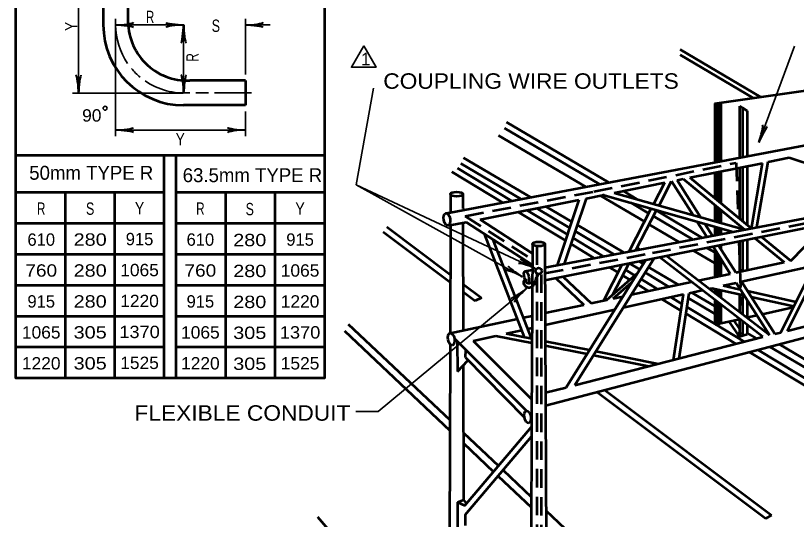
# Model space of a CAD drawing. Extents: x -111 to 744, y -77 to 467.
# Drawn here: x 347.6 to 499.2, y 245.3 to 343 of the extents above; entities that cross this region are included whole.
import ezdxf
from ezdxf.enums import TextEntityAlignment as Align

# ---------------------------------------------------------------- set-up
doc = ezdxf.new("R2010")
doc.units = 0
doc.header["$LTSCALE"] = 1.2
doc.header["$PDMODE"] = 32
doc.header["$PDSIZE"] = 0.6
doc.linetypes.add('MEDIUM_DASHED', pattern=[4.5, 3, -1.5])
doc.layers.add('1', color=7, linetype='Continuous', lineweight=53)

msp = doc.modelspace()

# ---------------------------------------------------------------- linework, layer by layer
at = {"layer": '1', "lineweight": 35}
for p, q in [((359.809, 353.245), (359.809, 328.032)), ((367.009, 342.445), (367.009, 341.245)), ((367.009, 341.247), (367.009, 319.645)), ((380.209, 341.232), (367.009, 341.232)), ((380.209, 341.232), (380.209, 328.045)), ((392.209, 331.645), (392.209, 342.432)), ((392.209, 341.232), (397.009, 341.232)), ((491.87, 318.43), (498.816, 337.139)), ((413.7, 310.233), (417.064, 329.002)), ((380.089, 328.032), (358.609, 328.032)), ((385.009, 328.045), (382.609, 328.045)), ((393.409, 328.045), (386.209, 328.045)), ((392.209, 324.445), (392.209, 319.645)), ((367.009, 320.845), (392.209, 320.845))]:
    msp.add_line(p, q, dxfattribs=at)
at = {"layer": '1'}
for p, q in [((364.609, 353.245), (364.609, 341.245)), ((369.409, 353.245), (369.409, 342.445)), ((476.605, 335.442), (490.82, 327.048)), ((476.62, 336.475), (492.239, 327.251)), ((483.311, 325.975), (534.911, 333.348)), ((392.209, 330.445), (381.409, 330.445)), ((392.209, 330.445), (392.209, 325.645)), ((483.311, 325.975), (483.311, 314.575)), ((483.39, 325.987), (483.39, 314.59)), ((483.501, 326.002), (483.501, 314.611)), ((483.649, 326.024), (483.649, 314.639)), ((483.708, 326.032), (483.708, 314.65)), ((483.708, 326.032), (483.708, 314.803)), ((483.708, 326.032), (483.708, 314.803)), ((483.853, 326.053), (483.853, 314.678)), ((483.926, 326.063), (483.926, 314.692)), ((484.072, 326.084), (484.072, 314.719)), ((484.072, 326.084), (484.072, 314.803)), ((484.131, 326.093), (484.131, 314.731)), ((484.29, 326.115), (484.29, 314.761)), ((484.29, 326.115), (484.29, 314.803)), ((484.427, 326.135), (484.427, 314.787)), ((484.511, 326.147), (484.511, 314.803)), ((392.209, 325.645), (380.209, 325.645)), ((488.111, 325.461), (488.111, 315.484)), ((488.711, 325.161), (488.711, 315.598)), ((489.611, 324.561), (489.611, 315.769)), ((442.904, 322.386), (462.732, 310.678)), ((441.356, 319.817), (458.265, 309.832)), ((442.5, 321.232), (460.945, 310.339)), ((347.594, 315.973), (407.594, 315.973)), ((376.394, 315.973), (376.394, 272.773)), ((378.793, 272.773), (378.793, 315.973)), ((434.556, 315.471), (447.544, 307.801)), ((450.352, 294.188), (564.73, 315.85)), ((493.673, 314.672), (497.792, 315.496)), ((497.792, 315.496), (521.683, 307.698)), ((434.05, 314.389), (445.739, 307.459)), ((478.481, 311.633), (492.601, 314.458)), ((490.424, 301.777), (492.601, 314.458)), ((491.494, 301.98), (493.673, 314.672)), ((432.272, 312.724), (442.115, 306.773)), ((433.36, 313.469), (443.881, 307.107)), ((483.311, 312.6), (483.311, 307.647)), ((483.39, 312.615), (483.39, 307.582)), ((483.538, 312.645), (483.538, 307.46)), ((483.708, 312.679), (483.708, 307.32)), ((483.708, 312.679), (483.708, 307.32)), ((483.708, 312.679), (483.708, 307.32)), ((483.708, 312.679), (483.708, 307.32)), ((483.926, 312.723), (483.926, 307.14)), ((483.926, 312.723), (483.926, 307.14)), ((483.999, 312.737), (483.999, 307.08)), ((484.144, 312.766), (484.144, 306.96)), ((484.144, 312.766), (484.144, 306.96)), ((484.242, 312.786), (484.242, 306.879)), ((484.363, 312.81), (484.363, 306.779)), ((484.511, 312.84), (484.511, 306.657)), ((488.111, 313.56), (488.111, 303.686)), ((488.711, 313.68), (488.711, 303.191)), ((489.611, 313.68), (489.611, 302.448)), ((472.509, 306.236), (474.942, 310.926)), ((474.942, 310.926), (479.107, 304.367)), ((476.014, 311.14), (477.191, 311.375)), ((476.014, 311.14), (480.58, 303.95)), ((477.191, 311.375), (489.121, 301.531)), ((478.481, 311.633), (490.424, 301.777)), ((463.813, 308.7), (473.622, 310.662)), ((471.478, 306.528), (473.622, 310.662)), ((347.594, 308.773), (376.394, 308.773)), ((357.194, 308.773), (357.194, 272.773)), ((366.793, 308.773), (366.793, 272.773)), ((378.793, 308.773), (407.594, 308.773)), ((388.394, 272.773), (388.394, 308.773)), ((397.994, 272.773), (397.994, 308.773)), ((431.997, 308.409), (431.997, 304.857)), ((434.421, 308.409), (434.421, 305.652)), ((458.328, 307.602), (461.858, 308.308)), ((461.101, 308.157), (469.691, 303.084)), ((461.62, 308.261), (461.858, 308.308)), ((461.62, 308.261), (486.878, 301.106)), ((463.813, 308.7), (489.121, 301.53)), ((465.508, 309.038), (468.173, 307.465)), ((437.754, 303.487), (456.957, 307.328)), ((456.957, 307.328), (452.733, 294.633)), ((458.328, 307.602), (454.101, 294.897)), ((467.088, 306.712), (470.522, 304.684)), ((483.311, 306.325), (483.311, 303.176)), ((483.36, 306.284), (483.36, 303.162)), ((483.42, 306.235), (483.42, 303.145)), ((434.421, 305.652), (434.805, 305.403)), ((445.115, 304.959), (454.317, 299.396)), ((446.858, 305.308), (454.706, 300.563)), ((448.734, 305.683), (455.145, 301.883)), ((450.524, 306.041), (455.543, 303.078)), ((466.681, 297.281), (470.999, 305.604)), ((467.992, 297.529), (472.03, 305.312)), ((471.98, 305.216), (480.869, 299.967)), ((483.507, 306.163), (483.507, 303.121)), ((483.574, 306.108), (483.574, 303.102)), ((483.647, 306.048), (483.647, 303.081)), ((483.754, 305.959), (483.754, 303.051)), ((483.814, 305.91), (483.814, 303.034)), ((483.907, 305.833), (483.907, 303.007)), ((483.987, 305.767), (483.987, 302.985)), ((484.108, 305.668), (484.108, 302.951)), ((484.234, 305.563), (484.234, 302.915)), ((484.328, 305.486), (484.328, 302.888)), ((484.408, 305.42), (484.408, 302.866)), ((484.461, 305.376), (484.461, 302.85)), ((484.511, 305.335), (484.511, 302.836)), ((437.754, 303.487), (447.909, 296.889)), ((471.427, 304.15), (479.082, 299.629)), ((497.433, 281.932), (508.11, 303.296)), ((347.594, 302.773), (376.394, 302.773)), ((378.793, 302.773), (407.594, 302.773)), ((419.639, 302.062), (431.975, 292.835)), ((431.541, 302.313), (435.084, 302.99)), ((431.997, 302.409), (431.949, 281.457)), ((434.421, 302.863), (434.469, 281.937)), ((435.084, 302.99), (447.892, 294.676)), ((450.362, 291.744), (505.078, 302.689)), ((456.612, 302.446), (465.681, 297.091)), ((470.597, 302.549), (476.402, 299.121)), ((479.928, 303.074), (481.79, 300.142)), ((481.401, 302.657), (482.869, 300.346)), ((483.311, 302.116), (483.311, 300.43)), ((483.364, 302.101), (483.364, 300.44)), ((483.421, 302.085), (483.421, 300.451)), ((483.492, 302.065), (483.492, 300.464)), ((483.549, 302.049), (483.549, 300.475)), ((483.651, 302.02), (483.651, 300.494)), ((483.753, 301.991), (483.753, 300.514)), ((483.849, 301.964), (483.849, 300.532)), ((483.938, 301.938), (483.938, 300.549)), ((484.021, 301.915), (484.021, 300.565)), ((484.072, 301.9), (484.072, 300.574)), ((484.155, 301.877), (484.155, 300.59)), ((484.238, 301.853), (484.238, 300.606)), ((484.334, 301.826), (484.334, 300.624)), ((484.423, 301.801), (484.423, 300.657)), ((484.461, 301.79), (484.461, 300.657)), ((484.511, 301.776), (484.511, 300.657)), ((496.126, 281.598), (506.843, 303.042)), ((498.066, 295.471), (505.078, 302.689)), ((418.92, 301.101), (431.972, 291.339)), ((446.38, 280.696), (438.607, 300.703)), ((456.214, 301.249), (463.821, 296.739)), ((492.394, 300.152), (498.066, 295.471)), ((447.832, 280.272), (440.328, 299.586)), ((447.909, 298.713), (447.765, 264.105)), ((450.332, 298.75), (450.465, 267.44)), ((455.383, 298.751), (459.931, 296.002)), ((455.772, 299.919), (461.697, 296.336)), ((488.111, 299.295), (488.111, 293.363)), ((488.711, 299.415), (488.711, 293.49)), ((489.611, 299.595), (489.611, 293.68)), ((491.104, 299.894), (496.791, 295.201)), ((450.465, 267.44), (569.111, 298.453)), ((468.233, 297.994), (468.762, 297.675)), ((479.145, 297.501), (483.311, 295.041)), ((481.789, 298.03), (483.311, 297.132)), ((482.98, 298.269), (486.334, 292.986)), ((483.311, 297.747), (483.311, 292.346)), ((483.38, 297.638), (483.38, 292.361)), ((483.442, 297.541), (483.442, 292.374)), ((483.504, 297.444), (483.504, 292.387)), ((483.556, 297.361), (483.556, 292.398)), ((483.599, 297.294), (483.599, 292.407)), ((483.675, 297.174), (483.675, 292.423)), ((484.052, 298.483), (487.399, 293.212)), ((484.108, 298.494), (484.108, 298.395)), ((484.155, 298.504), (484.155, 298.32)), ((484.217, 298.516), (484.217, 298.223)), ((484.265, 298.525), (484.265, 298.148)), ((484.331, 298.539), (484.331, 298.043)), ((484.36, 298.545), (484.36, 297.998)), ((484.407, 298.554), (484.407, 297.923)), ((484.469, 298.575), (484.469, 297.826)), ((484.511, 298.575), (484.511, 297.76)), ((347.594, 296.773), (376.394, 296.773)), ((378.793, 296.773), (407.594, 296.773)), ((454.457, 270.937), (469.937, 295.66)), ((456.141, 271.368), (471.564, 295.985)), ((492.669, 280.714), (472.569, 296.186)), ((493.924, 281.035), (473.896, 296.452)), ((483.746, 297.062), (483.746, 292.438)), ((483.794, 296.987), (483.794, 292.448)), ((483.846, 296.904), (483.846, 292.459)), ((483.898, 296.822), (483.898, 292.47)), ((483.932, 296.77), (483.932, 292.478)), ((483.989, 296.68), (483.989, 292.49)), ((484.027, 296.62), (484.027, 292.498)), ((484.093, 296.515), (484.093, 292.512)), ((484.165, 296.403), (484.165, 292.527)), ((484.231, 296.298), (484.231, 292.541)), ((484.293, 296.2), (484.293, 292.554)), ((484.35, 296.11), (484.35, 292.566)), ((484.365, 296.088), (484.365, 292.569)), ((484.417, 296.006), (484.417, 292.58)), ((484.474, 295.916), (484.474, 292.6)), ((484.511, 295.857), (484.511, 292.6)), ((461.753, 287.78), (465.366, 294.745)), ((462.844, 294.241), (464.564, 293.201)), ((463.537, 288.941), (466.685, 295.009)), ((466.698, 295.034), (468.774, 293.803)), ((468.568, 295.386), (469.442, 294.87)), ((470.481, 294.257), (476.248, 290.85)), ((487.399, 293.212), (496.791, 295.201)), ((488.506, 291.469), (502.615, 294.582)), ((446.493, 293.457), (447.885, 293.721)), ((462.356, 287.908), (468.385, 293.181)), ((465.464, 292.657), (466.837, 291.827)), ((466.018, 293.724), (467.785, 292.656)), ((469.811, 293.188), (474.41, 290.461)), ((480.11, 291.668), (486.334, 292.986)), ((447.093, 291.105), (447.885, 291.249)), ((452.445, 292.113), (457.9, 286.964)), ((453.909, 292.401), (459.345, 287.27)), ((463.614, 288.175), (467.23, 291.337)), ((467.138, 288.921), (478.799, 291.391)), ((469.133, 291.841), (472.192, 289.991)), ((484.947, 290.684), (487.446, 291.236)), ((487.446, 291.236), (493.924, 281.035)), ((488.506, 291.469), (494.963, 281.3)), ((347.594, 290.773), (376.394, 290.773)), ((378.793, 290.773), (407.594, 290.773)), ((434.448, 290.986), (438.012, 288.32)), ((468.376, 290.897), (470.475, 289.627)), ((478.35, 289.229), (480.881, 289.787)), ((482.181, 290.074), (482.722, 290.193)), ((482.722, 290.193), (488.988, 288.808)), ((483.311, 290.063), (483.311, 289.204)), ((483.367, 290.05), (483.367, 289.161)), ((483.438, 290.035), (483.438, 289.106)), ((483.492, 290.023), (483.492, 289.065)), ((483.575, 290.005), (483.575, 289.001)), ((483.658, 289.986), (483.658, 288.937)), ((483.735, 289.969), (483.735, 288.878)), ((483.807, 289.953), (483.807, 288.823)), ((483.878, 289.938), (483.878, 288.768)), ((483.955, 289.92), (483.955, 288.708)), ((484.026, 289.905), (484.026, 288.653)), ((484.092, 289.89), (484.092, 288.603)), ((484.169, 289.873), (484.169, 288.544)), ((484.229, 289.86), (484.229, 288.498)), ((484.306, 289.843), (484.306, 288.438)), ((484.371, 289.828), (484.371, 288.388)), ((484.431, 289.815), (484.431, 288.342)), ((484.466, 289.807), (484.466, 288.315)), ((484.511, 289.798), (484.511, 288.28)), ((484.947, 290.684), (488.262, 289.951)), ((485.568, 290.821), (486.307, 290.384)), ((489.667, 289.641), (499.102, 287.554)), ((434.452, 289.485), (436.789, 287.736)), ((438.012, 288.32), (436.789, 287.736)), ((463.614, 288.175), (465.5, 288.574)), ((465.563, 286.408), (477.282, 288.993)), ((473.064, 288.062), (476.791, 285.809)), ((474.763, 288.437), (476.989, 287.091)), ((475.323, 276.275), (477.282, 288.993)), ((476.397, 276.55), (478.35, 289.229)), ((478.194, 288.218), (483.311, 285.184)), ((478.819, 289.332), (483.311, 286.68)), ((488.111, 289.001), (488.111, 285.509)), ((488.711, 289.243), (488.711, 285.047)), ((490.393, 288.497), (498.66, 286.669)), ((450.389, 285.374), (457.9, 286.964)), ((459.345, 287.27), (462.356, 287.908)), ((483.311, 287.917), (483.311, 283.119)), ((483.391, 287.856), (483.391, 283.137)), ((483.462, 287.801), (483.462, 283.153)), ((483.509, 287.764), (483.509, 283.163)), ((483.557, 287.728), (483.557, 283.174)), ((483.652, 287.654), (483.652, 283.195)), ((483.723, 287.6), (483.723, 283.21)), ((483.819, 287.526), (483.819, 283.231)), ((483.89, 287.471), (483.89, 283.247)), ((483.996, 287.389), (483.996, 283.271)), ((484.104, 287.307), (484.104, 283.295)), ((484.184, 287.245), (484.184, 283.312)), ((484.247, 287.197), (484.247, 283.326)), ((484.294, 287.16), (484.294, 283.337)), ((484.365, 287.105), (484.365, 283.352)), ((484.447, 287.042), (484.447, 283.37)), ((484.511, 286.993), (484.511, 283.385)), ((489.611, 287.826), (489.611, 284.355)), ((492.516, 285.153), (498.571, 286.491)), ((450.399, 283.062), (463.917, 286.045)), ((477.735, 285.238), (487.434, 279.374)), ((347.594, 284.773), (376.394, 284.773)), ((378.793, 284.773), (407.594, 284.773)), ((431.938, 281.466), (445.006, 284.234)), ((446.195, 284.486), (447.851, 284.836)), ((483.311, 283.119), (488.153, 284.189)), ((488.111, 280.777), (486.134, 283.743)), ((488.111, 282.354), (487.051, 283.946)), ((488.111, 284.222), (488.111, 281.24)), ((488.711, 283.76), (488.711, 280.962)), ((489.453, 284.476), (491.457, 284.919)), ((497.433, 281.932), (507.931, 284.618)), ((412.177, 283.221), (431.894, 264.632)), ((442.849, 281.397), (445.85, 282.059)), ((447.036, 282.321), (447.841, 282.499)), ((489.611, 283.067), (489.611, 281.24)), ((411.412, 281.881), (431.889, 262.574)), ((436.403, 279.975), (440.824, 280.95)), ((440.824, 280.95), (447.829, 279.561)), ((442.849, 281.397), (447.833, 280.408)), ((456.141, 271.368), (492.669, 280.714)), ((489.611, 281.449), (491.4, 280.389)), ((494.963, 281.3), (496.126, 281.598)), ((431.925, 279.297), (431.703, 174.336)), ((432.778, 280.394), (446.757, 266.385)), ((433.338, 279.833), (433.365, 274.041)), ((436.403, 279.975), (447.784, 268.569)), ((450.412, 279.897), (459, 278.193)), ((450.416, 279.048), (458.528, 277.439)), ((495.817, 279.295), (611.923, 210.731)), ((347.594, 278.773), (376.394, 278.773)), ((378.793, 278.773), (407.594, 278.773)), ((434.901, 276.729), (434.972, 278.196)), ((460.26, 277.943), (472.416, 275.532)), ((490.056, 277.789), (607.956, 206.509)), ((491.676, 278.212), (608.519, 207.571)), ((494.032, 278.828), (611.923, 208.935)), ((433.365, 274.041), (435.406, 276.181)), ((434.901, 276.729), (446.367, 265.08)), ((459.788, 277.189), (470.549, 275.054)), ((434.49, 275.221), (434.565, 249.153)), ((450.454, 269.913), (454.457, 270.937)), ((460.438, 270.047), (493.247, 245.507)), ((461.923, 270.435), (494.365, 246.169)), ((450.465, 267.44), (450.713, 207.213)), ((447.765, 264.105), (447.573, 215.433)), ((434.829, 248.025), (447.765, 263.265)), ((434.528, 262.149), (441.355, 255.713)), ((434.877, 246.225), (447.765, 261.393)), ((434.534, 260.082), (440.382, 254.567)), ((442.234, 254.883), (447.708, 249.722)), ((441.262, 253.739), (447.7, 247.669)), ((433.365, 248.649), (434.565, 249.153)), ((433.365, 248.649), (433.365, 242.001)), ((433.365, 248.649), (434.829, 248.025)), ((434.565, 249.153), (435.093, 248.337)), ((406.184, 245.825), (431.792, 216.367)), ((434.877, 246.225), (434.877, 244.137)), ((450.549, 247.044), (535.801, 166.67)), ((494.365, 246.169), (493.247, 245.507))]:
    msp.add_line(p, q, dxfattribs=at)
at = {"layer": '1', "linetype": 'MEDIUM_DASHED'}
for p, q in [((459.861, 308.913), (487.487, 314.511)), ((487.487, 314.511), (487.843, 303.907)), ((434.87, 304.178), (459.861, 308.913)), ((434.87, 304.178), (447.896, 295.714)), ((487.999, 299.272), (488.417, 286.834)), ((448.797, 298.324), (448.797, 206.623)), ((449.609, 292.857), (449.609, 206.873))]:
    msp.add_line(p, q, dxfattribs=at)
at = {"layer": '1'}
msp.add_lwpolyline([(407.594, 392.773), (347.594, 392.773), (347.594, 272.773), (407.594, 272.773)], close=True, dxfattribs=at)
for points in [[(431.101, 304.698), (431.997, 304.857), (612.156, 338.978)], [(488.111, 325.461), (488.711, 325.161), (489.611, 324.561)], [(477.933, 286.521), (483.311, 283.269), (489.064, 279.791)], [(488.111, 281.24), (488.111, 280.777), (489.611, 281.24)]]:
    msp.add_lwpolyline(points, dxfattribs=at)
at = {"layer": '1', "lineweight": 35}
msp.add_lwpolyline([(415.175, 337.184), (412.775, 333.027), (417.575, 333.027)], close=True, dxfattribs=at)
at = {"layer": '1', "linetype": 'MEDIUM_DASHED'}
msp.add_lwpolyline([(450.353, 293.059), (471.201, 297.019), (573.774, 316.904)], dxfattribs=at)
at = {"layer": '1', "lineweight": 35}
for points in [[(448.536, 293.962), (413.7, 310.233), (445.961, 292.402)], [(446.774, 290.097), (417.97, 266.233), (413.632, 266.233)]]:
    msp.add_lwpolyline(points, dxfattribs=at)
msp.add_circle((364.974, 325.09), 0.387, dxfattribs=at)
at = {"layer": '1'}
msp.add_circle((449.126, 293.521), 0.605, dxfattribs=at)
for centre, radius, start, end in [((380.223, 341.26), 15.614, 180.05297, 269.94703), ((380.965, 342.002), 11.565, 177.80196, 272.19803)]:
    msp.add_arc(centre, radius, start, end, dxfattribs=at)
at = {"layer": '1', "lineweight": 35}
for start, end in [(180.05297, 214.53594), (219.78967, 230.21033), (235.46406, 275.14734)]:
    msp.add_arc((380.223, 341.26), 13.214, start, end, dxfattribs=at)
at = {"layer": '1', "lineweight": 40}
for centre, major_axis, ratio, start_param, end_param in [((368.318, 341.563), (-2.143, -0.187), 0.122415, 0.8963533, 3.1415927), ((368.318, 341.563), (-2.143, -0.187), 0.122415, 0.8963533, 3.1415927), ((368.354, 340.978), (-2.108, 0.211), 0.07063, 3.1407148, 5.41811), ((368.354, 340.978), (-2.108, 0.211), 0.07063, 3.1407148, 5.41811), ((378.899, 340.9), (2.143, 0.187), 0.122415, 0.8963533, 3.1415927), ((378.899, 340.9), (2.143, 0.187), 0.122415, 0.8963533, 3.1415927), ((378.864, 341.486), (2.108, -0.211), 0.07063, 3.1407148, 5.41811), ((378.864, 341.486), (2.108, -0.211), 0.07063, 3.1407148, 5.41811), ((379.955, 339.887), (0.211, 2.108), 0.07063, 3.1407148, 5.41811), ((379.955, 339.887), (0.211, 2.108), 0.07063, 3.1407148, 5.41811), ((380.54, 339.922), (-0.187, 2.143), 0.122415, 0.8963533, 3.1415927), ((380.54, 339.922), (-0.187, 2.143), 0.122415, 0.8963533, 3.1415927), ((393.518, 341.563), (-2.143, -0.187), 0.122415, 0.8963533, 3.1415927), ((393.518, 341.563), (-2.143, -0.187), 0.122415, 0.8963533, 3.1415927), ((393.554, 340.978), (-2.108, 0.211), 0.07063, 3.1407148, 5.41811), ((393.554, 340.978), (-2.108, 0.211), 0.07063, 3.1407148, 5.41811), ((359.477, 329.341), (0.187, -2.143), 0.122415, 0.8963533, 3.1415927), ((359.477, 329.341), (0.187, -2.143), 0.122415, 0.8963533, 3.1415927), ((360.063, 329.376), (-0.211, -2.108), 0.07063, 3.1407148, 5.41811), ((360.063, 329.376), (-0.211, -2.108), 0.07063, 3.1407148, 5.41811), ((379.877, 329.355), (0.187, -2.143), 0.122415, 0.8963533, 3.1415927), ((379.877, 329.355), (0.187, -2.143), 0.122415, 0.8963533, 3.1415927), ((380.463, 329.39), (-0.211, -2.108), 0.07063, 3.1407148, 5.41811), ((380.463, 329.39), (-0.211, -2.108), 0.07063, 3.1407148, 5.41811), ((368.318, 321.177), (-2.143, -0.187), 0.122415, 0.8963533, 3.1415927), ((368.318, 321.177), (-2.143, -0.187), 0.122415, 0.8963533, 3.1415927), ((492.015, 319.773), (-0.57, -2.074), 0.122415, 0.8963533, 3.1415927), ((492.576, 319.602), (0.931, 1.903), 0.07063, 6.2823074, 8.5597026), ((368.354, 320.591), (-2.108, 0.211), 0.07063, 3.1407148, 5.41811), ((368.354, 320.591), (-2.108, 0.211), 0.07063, 3.1407148, 5.41811), ((390.899, 320.514), (2.143, 0.187), 0.122415, 0.8963533, 3.1415927), ((390.864, 321.099), (2.108, -0.211), 0.07063, 3.1407148, 5.41811), ((447.425, 294.761), (1.821, -1.083), 0.07063, 3.1407148, 5.41811), ((447.425, 294.761), (1.821, -1.083), 0.07063, 3.1407148, 5.41811), ((444.907, 293.275), (-1.743, 1.204), 0.07063, 6.2823074, 8.5597026), ((447.21, 294.215), (2.021, -0.737), 0.122415, 0.8963533, 3.1415927), ((447.21, 294.215), (2.021, -0.737), 0.122415, 0.8963533, 3.1415927), ((444.654, 292.745), (1.966, -0.873), 0.122415, 0.8963533, 3.1415927), ((445.577, 289.435), (-1.758, -1.182), 0.07063, 6.2823074, 8.5597026), ((445.977, 289.006), (1.531, 1.511), 0.122415, 0.8963533, 3.1415927)]:
    msp.add_ellipse(centre, major_axis=major_axis, ratio=ratio, start_param=start_param, end_param=end_param, dxfattribs=at)
at = {"layer": '1'}
for centre, major_axis, ratio in [((433.21, 308.41), (1.21, 0), 0.366793), ((431.326, 303.51), (0.225, -1.188), 0.516919), ((449.133, 298.75), (1.21, 0), 0.366793), ((446.794, 292.282), (0.302, -1.174), 0.357898), ((432.163, 280.278), (0.225, -1.188), 0.517636), ((446.982, 265.196), (0.225, -1.188), 0.517636)]:
    msp.add_ellipse(centre, major_axis=major_axis, ratio=ratio, dxfattribs=at)
msp.add_spline([(449.085, 293.001), (448.989, 292.785), (448.965, 292.713), (448.677, 292.233), (448.557, 291.849), (448.413, 291.417), (448.365, 291.177), (448.317, 291.033), (448.173, 290.769), (447.981, 290.601), (447.717, 290.361), (447.381, 290.241), (447.141, 290.241), (446.805, 290.361), (446.589, 290.529), (446.421, 290.793), (446.325, 290.913), (446.253, 291.225), (446.253, 291.513), (446.541, 291.729), (446.829, 291.825), (446.973, 291.825)], degree=3, dxfattribs=at)
msp.add_point((488.111, 281.24), dxfattribs=at)

# ---------------------------------------------------------------- texts
for s, height, width, p in [('R', 2.4, 0.7, (372.9, 341.584)), ('S', 2.4, 0.75, (385.665, 339.882)), ('COUPLING WIRE OUTLETS', 3, 1.1, (418.967, 328.856)), ('90', 2.4, 1.05, (360.506, 322.483)), ('Y', 2.4, 0.85, (378.644, 317.908)), ('FLEXIBLE CONDUIT', 3, 1.1, (370.663, 264.47))]:
    msp.add_text(s, height=height, dxfattribs=dict(at, width=width)).set_placement(p)
for s, width, p in [('Y', 0.85, (359.549, 340.041)), ('R', 0.7, (383.112, 334.136))]:
    msp.add_text(s, height=2.4, rotation=90, dxfattribs=dict(at, width=width)).set_placement(p)
for s, height, p in [('1', 2.4, (414.667, 333.434)), ('50mm TYPE R', 2.7, (350.242, 311.208)), ('63.5mm TYPE R', 2.7, (380.03, 310.741))]:
    msp.add_text(s, height=height, dxfattribs=at).set_placement(p)
for s, width, p in [('R', 0.7, (352.566, 304.408)), ('S', 0.75, (362.066, 304.408)), ('Y', 0.85, (371.654, 304.497)), ('R', 0.7, (383.461, 304.408)), ('S', 0.75, (393.049, 304.319)), ('Y', 0.85, (402.815, 304.408)), ('280', 1.2, (362.066, 298.408)), ('280', 1.2, (393.049, 298.319)), ('760', 1.15, (352.566, 292.408)), ('280', 1.2, (362.066, 292.408)), ('1065', 1.05, (371.654, 292.497)), ('760', 1.15, (383.461, 292.408)), ('280', 1.2, (393.049, 292.319)), ('1065', 1.05, (402.815, 292.408)), ('280', 1.2, (362.066, 286.408)), ('1220', 1.05, (371.654, 286.497)), ('280', 1.2, (393.049, 286.319)), ('1220', 1.05, (402.815, 286.408)), ('1065', 1.05, (352.566, 280.408)), ('305', 1.2, (362.066, 280.408)), ('1370', 1.1, (371.654, 280.497)), ('1065', 1.05, (383.461, 280.408)), ('305', 1.2, (393.049, 280.319)), ('1370', 1.1, (402.815, 280.408)), ('1220', 1.05, (352.566, 274.408)), ('305', 1.2, (362.066, 274.408)), ('1525', 1.05, (371.654, 274.497)), ('1220', 1.05, (383.461, 274.408)), ('305', 1.2, (393.049, 274.319)), ('1525', 1.05, (402.815, 274.408))]:
    msp.add_text(s, height=2.4, dxfattribs=dict(at, width=width)).set_placement(p, align=Align.CENTER)
for s, p in [('610', (352.566, 298.408)), ('915', (371.654, 298.497)), ('610', (383.461, 298.408)), ('915', (402.815, 298.408)), ('915', (352.566, 286.408)), ('915', (383.461, 286.408))]:
    msp.add_text(s, height=2.4, dxfattribs=at).set_placement(p, align=Align.CENTER)

doc.saveas('drawing.dxf')
